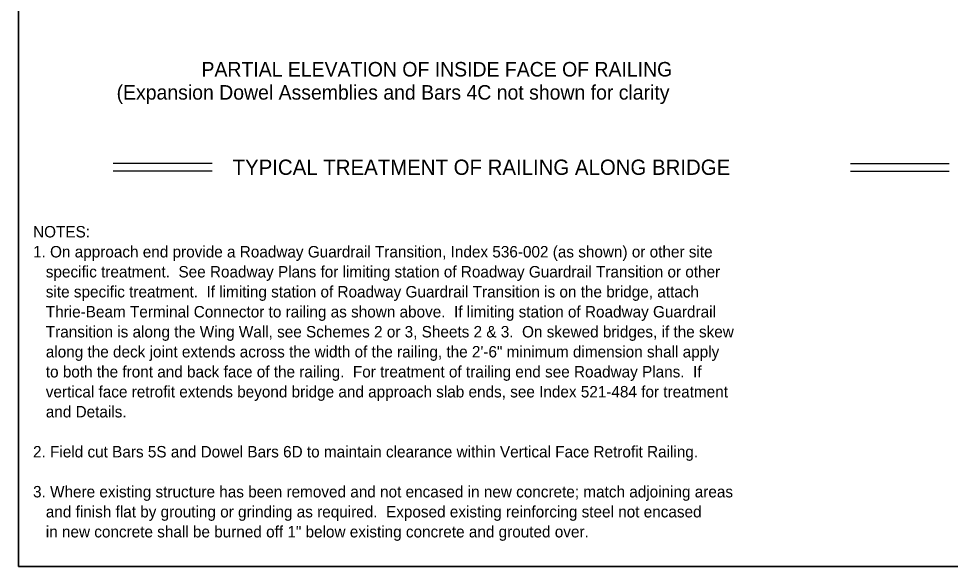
# Model space of a CAD drawing. Extents: x 0 to 41.1, y 0 to 25.9.
# Drawn here: x 0 to 16.42, y 0 to 9.64 of the extents above; entities that cross this region are included whole.
import ezdxf

# ---------------------------------------------------------------- set-up
doc = ezdxf.new("R2010")
doc.units = 0
for name, color, linetype in [('Dimension', 7, 'Continuous'), ('Miscellaneous1', 7, 'Continuous'), ('TextStructures', 7, 'Continuous')]:
    doc.layers.add(name, color=color, linetype=linetype)

msp = doc.modelspace()

# ---------------------------------------------------------------- linework, layer by layer
at = {"layer": 'Dimension'}
for p, q in [((3.409, 7.093), (1.666, 7.093)), ((14.654, 7.093), (16.398, 7.093)), ((3.409, 6.957), (1.666, 6.957)), ((14.654, 6.957), (16.398, 6.957))]:
    msp.add_line(p, q, dxfattribs=at)
msp.add_lwpolyline([(0, 0), (41.051, 0), (41.051, 25.946), (0, 25.946)], close=True, dxfattribs=at)
at = {"layer": 'Miscellaneous1'}
msp.add_lwpolyline([(0, 25.946), (41.051, 25.946), (41.051, 0), (0, 0)], close=True, dxfattribs=at)

# ---------------------------------------------------------------- texts
at = {"layer": 'Dimension'}
for s, height, p in [('PARTIAL ELEVATION OF INSIDE FACE OF RAILING', 0.256, (3.222, 8.622)), ('(Expansion Dowel Assemblies and Bars 4C not shown for clarity', 0.256, (1.726, 8.215)), ('NOTES:', 0.2016, (0.254, 5.789)), ('1. On approach end provide a Roadway Guardrail Transition, Index 536-002 (as shown) or other site ', 0.2016, (0.254, 5.437)), ('   specific treatment.  See Roadway Plans for limiting station of Roadway Guardrail Transition or other ', 0.2016, (0.254, 5.085)), ('   site specific treatment.  If limiting station of Roadway Guardrail Transition is on the bridge, attach ', 0.2016, (0.254, 4.733)), ('   Thrie-Beam Terminal Connector to railing as shown above.  If limiting station of Roadway Guardrail ', 0.2016, (0.254, 4.381)), ('   Transition is along the Wing Wall, see Schemes 2 or 3, Sheets 2 & 3.  On skewed bridges, if the skew ', 0.2016, (0.254, 4.029)), ('   along the deck joint extends across the width of the railing, the 2\'-6" minimum dimension shall apply ', 0.2016, (0.254, 3.677)), ('   to both the front and back face of the railing.  For treatment of trailing end see Roadway Plans.  If ', 0.2016, (0.254, 3.325)), ('   vertical face retrofit extends beyond bridge and approach slab ends, see Index 521-484 for treatment ', 0.2016, (0.254, 2.973)), ('   and Details.', 0.2016, (0.254, 2.621)), ('2. Field cut Bars 5S and Dowel Bars 6D to maintain clearance within Vertical Face Retrofit Railing.', 0.2016, (0.254, 1.917)), ('3. Where existing structure has been removed and not encased in new concrete; match adjoining areas ', 0.2016, (0.254, 1.213)), ('   and finish flat by grouting or grinding as required.  Exposed existing reinforcing steel not encased ', 0.2016, (0.254, 0.861)), ('   in new concrete shall be burned off 1" below existing concrete and grouted over.', 0.2016, (0.254, 0.509))]:
    msp.add_text(s, height=height, dxfattribs=at).set_placement(p)
at = {"layer": 'TextStructures'}
msp.add_text('TYPICAL TREATMENT OF RAILING ALONG BRIDGE', height=0.2688, dxfattribs=at).set_placement((3.77, 6.891))

doc.saveas('drawing.dxf')
